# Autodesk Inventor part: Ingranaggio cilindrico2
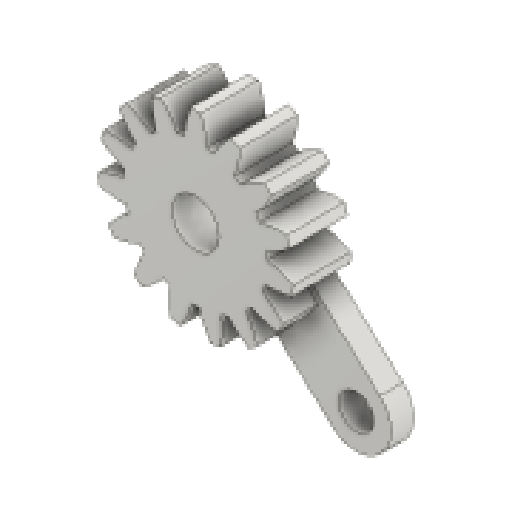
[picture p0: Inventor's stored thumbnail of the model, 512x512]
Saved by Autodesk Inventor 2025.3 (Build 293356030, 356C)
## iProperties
CustomPartVersion: 1
Created: 2026-03
Part Number: Ingranaggio cilindrico2
Material: Steel
Document SubType Name: Modeling
Designer: R5800u
Categories: <?xml version="1.0" encoding="UTF-16"?> <MemberInstance><Categories><FamilyTemplate><FamilyTemplateParameter ValueType="xs:double" Id="1" ObjectReferenceKey="da
Density: 1 g/cm^3
Appearance: Steel
Author: R5800u
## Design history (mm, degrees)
sketch "Sketch1"
  geometry: C1 r 8.5 at (0, 0)
  constraints: 1 centre point
  dimensions: "d0" = 17 diameter of C1 (= da_da)
extrude "Extrusion1" new body sketch "Sketch1" distance "d1" = 5 (= da_b); taper "d2" = 0 deg
workplane "Work Plane2"
feature "Diametro primitivo" dims "d4" = 10, "d5" = 0
workplane "Work Plane8"
workplane "Work Plane9"
feature "Ingranaggio cilindrico" dims "da_b" = 5, "da_d" = 15, "da_aw" = 15, "da_da" = 17, "da_df" = 12.5, "da_dw" = 15, angle "da_beta" = 0 deg, "da_lefttooth" = 0, "da_righttooth" = 0
sketch "Schizzo3"
  geometry: A1 r 6.25 centre (0, 0) between (-6.173, 0.978) and (-6.241, 0.327) reference; 2 further points
  constraints: 1 coincident
hole "Foro1" sketch "Schizzo3" at (0, 0) diameter "d49" = 4.1; stored, may be unused: countersink angle "d53" = 90 deg, drill point angle "d55" = 118 deg; dims "d50" = 6, "d51" = 5.5, "d52" = 2.9, "d54" = 8
sketch "Schizzo4"
  geometry: L1 (0, 0)-(-14.318, -13.284); L2 (2.674, -1.612)-(-12.277, -15.483); L3 (-1.407, 2.787)-(-16.358, -11.085); C1 r 1.6 at (-14.318, -13.284) reference; C2 r 2.05 at (0, 0) reference; C3 r 3 at (-10.996, -10.202); C4 r 1.5 at (-10.996, -10.202); A1 r 7.077 centre (-8.037, 2.389) between (-7.129, -4.629) and (-4.857, -3.933) reference; 9 further points
  constraints: 6 end point, 2 centre point, 2 coincident, 2 parallel, 1 point on line, 1 tangent, 3 other
  dimensions: "d56" = 3 distance between parallel lines of L1 L2; "d57" = 3 distance between parallel lines of L1 L3; "d61" = 3 diameter of C4; "d62" = 15 distance of point (0, 0) C3.centre
  node "Riferimento1"
node "Piano di lavoro11"
extrude "Estrusione2" join sketch "Schizzo4" stored distance "d59" = 10; taper "d60" = 0 deg
body "Solid1"
sketch "Sketch2"
  geometry: C1 r 8.5 at (0, 0) reference; C2 r 7.5 at (0, 0)
  constraints: 1 centre point, 1 coincident
  dimensions: "d3" = 15 diameter of C2 (= da_d)
body "Srf1"
other parameters: "d16" = 15 (= da_aw), "d17" = 0, "d34" = 12 deg (computed from da_z), "d39" = 0, "d41" = 0, "d43" = 15 (= da_aw), "d46" = 15 (= da_aw), "d47" = 0, "d48" = 0
